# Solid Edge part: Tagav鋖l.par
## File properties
Author: Türk
Template: Iso Part.par
Last saved by: Türk
Revision: 29
Application: Solid Edge
Accuracy: 0,990
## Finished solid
Body 1: solid body, 43 faces, 98 edges, 56 vertices.
  Faces by surface: plane 28, cylinder 15
  Edges by curve: line 68, circle 30
Bounding box of the edges (mm): 64.000 x 403.500 x 64.000, from (-32, -183.5, -32) to (32, 220, 32).
Cylindrical faces by radius (mm): R7.5 x4, R10 x8, R27.5 x1, R32 x2
Planar faces by outward normal: +x 4, +y 4, +z 4, -x 4, -y 4, -z 4, oblique 4
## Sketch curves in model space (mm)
line (-27.5, 170, -27.5) -> (-27.5, 170, 27.5)
line (-27.5, 170, 27.5) -> (27.5, 170, 27.5)
line (27.5, 170, 27.5) -> (27.5, 170, -27.5)
line (27.5, 170, -27.5) -> (-27.5, 170, -27.5)
line (-27.5, 220, 0) -> (-27.5, 205, 0)
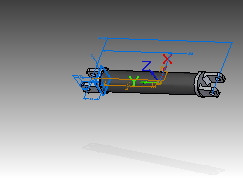
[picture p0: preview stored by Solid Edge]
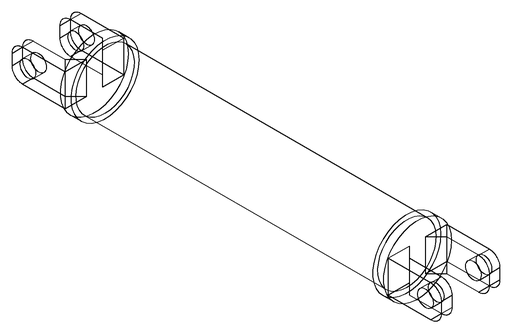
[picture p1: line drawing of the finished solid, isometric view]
